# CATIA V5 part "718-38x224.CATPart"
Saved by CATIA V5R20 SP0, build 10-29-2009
Part number: 718-38x224
Definition: NONE
Nomenclature: 718-38x224
Source: Unknown
Description: 718-38x224
Bounding box of the stored display mesh (mm): x 0 to 261, y -25 to 25, z -25 to 25
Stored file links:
  C:\Users\Utente\Desktop\IO LAVORO\3D X SITO CF\X SITO\718\718-38x224.CATPart

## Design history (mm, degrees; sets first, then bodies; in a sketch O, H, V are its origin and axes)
Body1 "718-38x224" (main body)
  Solid1: solid without history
